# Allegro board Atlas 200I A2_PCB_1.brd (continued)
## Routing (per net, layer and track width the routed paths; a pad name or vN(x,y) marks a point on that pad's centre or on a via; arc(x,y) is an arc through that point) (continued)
HDMI0_TXC_P: length 58.3
  TOP w0.155: v1(65.62,16.61) 65.38,16.37 65.38,16.15 R332.1 ; J16.224 41.75,49.7 41.69,49.76 41.69,50.58 v1(41.96,50.85)
  ART04 w0.14: v1(41.96,50.85) 41.71,50.6 41.71,45.32 40.65,44.26 39.71,44.26 39.54,44.09 39.54,43.79 39.71,43.62 40.65,43.62 41.03,43.24 41.61,41.85 41.37,41.27 40.89,41.07 40.81,40.87 40.93,40.59 41.13,40.5 41.61,40.7 42.11,40.49 42.2,40.27 42.55,39.93 42.75,39.93 43.29,40.47 43.86,40.47 44.29,40.03 44.29,39.47 43.75,38.93 43.75,38.72 45.44,37.04 46.08,36.77 48.25,36.77 49.27,35.75 49.27,35.22 49.64,34.85 51.89,33.92 53.04,33.92 58.52,31.65 59.64,30.9 60.5,30.54 63.24,28.71 64.7,26.53 65.69,24.12 65.96,22.79 65.96,19.71 65.38,18.32 65.38,16.85 v1(65.62,16.61)
HDMI1_CEC: length 73.3
  TOP w0.203: J16.235 39,54.19 39.45,53.75 v1(39.45,53.19) ; v1(75.95,16.1) 75.95,15.11 76.15,14.91 R299.1 R298.2
  ART03 w0.203: v1(39.45,53.19) 39.93,52.7 41.49,52.7 42.02,53.24 46.85,53.24 47.9,52.19 47.9,45.67 49.35,44.22 51.41,44.22 52.93,42.7 53.58,42.7 54.69,41.59 54.69,40.89 55.02,40.56 55.02,34.77 55.32,34.46 55.32,33.57 56.99,31.9 61.12,31.9 62.65,30.38 v1(62.65,29.79)
  BOTTOM w0.203: v1(62.65,29.79) 62.65,29.82 63.07,30.24 63.07,30.24 63.07,30.41 63.65,30.99 67.94,30.99 70.33,28.59 70.33,27.54 77.22,20.66 77.22,17.38 v1(75.95,16.1)
HDMI1_HOTPLUG: length 81.7
  TOP w0.203: v1(78.79,17.65) 78.92,17.78 83.13,17.78 83.74,17.17 R304.2 C145.1 83.77,15.57 R305.2 R303.1 ; v1(39.47,54.46) 39.5,54.49 J16.233
  ART03 w0.203: v1(65.1,29.82) 65.1,30.28 63.96,31.42 62.76,31.42 60.82,33.35 58.08,33.35 57.1,34.33 57.1,34.35 56.83,34.62 56.81,34.62 56.19,35.25 56.19,37.51 56.34,37.66 56.34,38.04 56.11,38.26 56.11,43.55 54.16,45.49 49.23,45.49 48.82,45.9 48.82,52.42 47.16,54.08 39.85,54.08 v1(39.47,54.46)
  BOTTOM w0.203: v1(65.1,29.82) 65.1,30.38 65.3,30.58 67.77,30.58 69.93,28.42 69.93,27.37 75.21,22.09 75.21,20.52 76.17,19.56 76.17,17.32 75.49,16.64 75.49,15.91 75.76,15.65 76.78,15.65 v1(78.79,17.65)
HDMI1_SCL: length 51.6
  TOP w0.203: J16.27 91,53.57 v1(89.35,51.92) ; R300.1 v1(75.95,13.89) R297.2
  ART03 w0.203: v1(75.95,13.89) 75.46,14.38 75.46,26.12 v1(85.06,35.72)
  ART04 w0.203: v1(85.06,35.72) 85.06,36.94 90.22,42.1 90.22,45.82 90.73,46.33 90.73,47.51 89.31,48.93 89.31,51.88 v1(89.35,51.92)
HDMI1_SDA: length 53
  TOP w0.203: R301.1 v1(75.95,12.88) R302.2 ; J16.29 90.5,54.34 v1(89.35,53.19)
  ART03 w0.203: v1(75.95,12.88) 76.81,13.74 76.81,17.25 76.19,17.87 76.19,25.21 85.06,34.09 v1(85.06,34.45)
  ART04 w0.203: v1(85.06,34.45) 85.7,35.09 85.7,36.03 89.48,39.82 89.48,40.72 90.67,41.91 90.67,45.49 91.19,46 91.19,47.7 89.77,49.12 89.77,51.29 89.83,51.36 89.83,52.7 v1(89.35,53.19)
HDMI1_TX0_C_N: length 6.1
  TOP w0.155: R364.2 87.35,15.27 87.35,15 87.73,14.62 87.98,14.62 88.14,14.47 88.14,14.09 D23.7 D23.4 88.08,12.85 88.22,12.7 88.22,12.4 87.98,12.16 J7.9
HDMI1_TX0_C_P: length 6
  TOP w0.155: J7.7 88.98,12.44 88.58,12.84 D23.5 D23.6 88.52,14.09 88.52,14.63 88.14,15 87.89,15 87.73,15.16 87.73,15.44 R397.2
HDMI1_TX0_N: length 44.2
  TOP w0.155: J16.17 93.5,54.97 93.56,54.91 93.56,52.65 v1(93.29,52.37) ; R364.1 87.27,16.7 87.27,17.88 v1(87,18.15)
  ART04 w0.14: v1(93.29,52.37) 93.81,51.85 93.81,47.33 93.4,46.35 93.4,36.52 91.06,34.17 90.31,33.86 89.64,33.2 88.7,30.93 88.7,29.88 89.12,29.47 89.12,29.04 88.7,28.63 88.7,27.85 89.12,27.44 89.12,27.01 88.7,26.6 88.7,25.82 89.12,25.4 89.12,24.98 88.7,24.57 88.7,20.87 87.27,19.44 87.27,18.42 v1(87,18.15)
HDMI1_TX0_P: length 44.3
  TOP w0.155: R397.1 87.65,16.7 87.65,17.88 v1(87.91,18.15) ; J16.15 94,54.95 93.94,54.89 93.94,52.64 v1(94.21,52.37)
  ART04 w0.14: v1(87.91,18.15) 87.66,18.4 87.66,19.26 89.09,20.69 89.09,21.38 89.28,21.57 89.28,22.01 89.09,22.2 89.09,22.62 89.28,22.81 89.28,23.25 89.09,23.44 89.09,24.39 89.5,24.8 89.5,25.58 89.09,25.99 89.09,26.42 89.5,26.83 89.5,27.62 89.09,28.03 89.09,28.45 89.5,28.86 89.5,29.65 89.09,30.06 89.09,30.81 89.98,32.97 90.53,33.52 91.28,33.84 93.78,36.34 93.78,46.24 94.19,47.22 94.19,52.35 v1(94.21,52.37)
HDMI1_TX1_C_N: length 5.5
  TOP w0.155: J7.6 89.48,12.4 89.63,12.55 D21.1 D21.10 89.63,14.36 89.68,14.41 89.68,15.34 R360.2
HDMI1_TX1_C_P: length 5.6
  TOP w0.155: R361.2 90.06,15.38 90.06,14.4 90.13,14.34 D21.9 D21.2 90.07,13.14 90.07,12.5 90.48,12.09 J7.4
HDMI1_TX1_N: length 44.9
  TOP w0.155: v1(94.79,53.82) 95.06,54.09 95.06,54.91 95,54.97 J16.11 ; R360.1 89.66,16.7 89.66,17.37 89.51,17.53 v1(89.4,17.53)
  ART04 w0.14: v1(94.79,53.82) 95.07,53.53 95.07,49.06 95.32,48.47 95.32,44.67 94.47,43.82 94.47,33.78 93,32.31 93,30.94 92.83,30.77 92.75,30.77 92.37,30.4 92.37,29.74 92.75,29.37 92.83,29.37 93,29.2 93,28.91 92.83,28.74 92.75,28.74 92.37,28.36 92.37,27.71 92.75,27.34 92.83,27.34 93,27.17 93,26.87 92.83,26.7 92.75,26.7 92.37,26.33 92.37,25.68 92.75,25.31 92.83,25.31 93,25.14 93,23.28 90.92,21.2 90.63,21.2 90.34,20.9 90.34,20.62 89.65,19.93 89.65,17.77 v1(89.4,17.53)
HDMI1_TX1_P: length 44.8
  TOP w0.155: v1(95.71,53.82) 95.44,54.09 95.44,54.89 95.5,54.95 J16.9 ; v1(90.31,17.53) 90.2,17.53 90.05,17.37 90.05,16.7 R361.1
  ART04 w0.14: v1(95.71,53.82) 95.45,53.56 95.45,49.14 95.7,48.54 95.7,44.51 94.85,43.67 94.85,33.6 93.38,32.13 93.38,30.76 93.01,30.39 92.93,30.39 92.76,30.22 92.76,29.92 92.93,29.75 93.01,29.75 93.38,29.38 93.38,28.73 93.01,28.36 92.93,28.36 92.76,28.18 92.76,27.89 92.93,27.72 93.01,27.72 93.38,27.35 93.38,26.69 93.01,26.32 92.93,26.32 92.76,26.15 92.76,25.86 92.93,25.69 93.01,25.69 93.38,25.32 93.38,23.1 90.03,19.75 90.03,17.81 v1(90.31,17.53)
HDMI1_TX2_C_N: length 6.2
  TOP w0.155: R349.2 92.1,15.32 92.1,15.14 91.97,15.01 91.63,15.01 91.13,14.51 D21.7 D21.4 91.08,13.15 91.08,12.75 91.19,12.65 91.19,12.24 90.98,12.04 J7.3
HDMI1_TX2_C_P: length 6.1
  TOP w0.155: J7.1 91.98,11.79 92,11.81 92,12.32 91.63,12.69 D21.5 D21.6 91.63,14.47 91.79,14.63 92.18,14.63 92.48,14.94 92.48,15.4 R359.2
HDMI1_TX2_N: length 44.7
  TOP w0.155: J16.5 96.5,54.97 96.56,54.91 96.56,52.65 v1(96.29,52.37) ; v1(91.8,18.15) 92.06,17.88 92.06,16.7 R349.1
  ART04 w0.14: v1(96.29,52.37) 96.55,52.11 96.55,51.69 97.74,50.5 97.74,46.28 99.71,44.32 100.69,41.94 100.69,33.69 99.84,31.63 97.77,28.54 97.77,28.54 95.69,25.42 94.75,23.16 92.05,20.46 92.05,18.4 v1(91.8,18.15)
HDMI1_TX2_P: length 44.7
  TOP w0.155: R359.1 92.44,16.7 92.44,17.88 v1(92.71,18.15) ; v1(97.21,52.37) 96.94,52.64 96.94,54.89 97,54.95 J16.3
  ART04 w0.14: v1(92.71,18.15) 92.71,18.17 92.44,18.44 92.44,20.3 95.08,22.94 96.03,25.24 100.18,31.45 101.07,33.62 101.07,42.02 100.03,44.54 98.13,46.44 98.13,50.66 96.93,51.85 96.93,52.09 v1(97.21,52.37)
HDMI1_TX_5V: length 17.3
  TOP w0.203: 80.26,13.26 C144.1 81.61,12.75 82.32,13.46 R303.2 82.96,12.88 v1(82.88,12.8) 83.48,12.2 J7.18 ; 80.26,13.26 80.14,13.39 78.65,13.39 78.36,13.09 78.36,12.45 77.57,11.66 76.93,11.66 76.62,11.35 D25.3 75.34,11.35 74.45,12.24 R302.1 R297.1 ; 80.26,13.26 80.54,13.54 U29.5
HDMI1_TX_CEC: length 14.2
  TOP w0.203: v1(85.46,12.82) 85.46,12.23 85.98,11.71 J7.13 ; R299.2 78.16,15.6 78.16,15.98 78.71,16.54 78.71,16.55 v1(78.77,16.61) 78.98,16.82 U29.3
  ART03 w0.203: v1(85.46,12.82) 85.46,12.93 84.85,13.54 84.12,13.54 83.46,14.2 81.19,14.2 v1(78.77,16.61)
HDMI1_TX_DDC_SCL_C: length 13.1
  TOP w0.203: U29.6 81.49,15.16 81.29,15.37 78.99,15.37 78.16,14.53 78.16,14.35 77.7,13.89 R300.2 ; J7.15 v1(84.98,12)
  TOP w0.254: U29.6 v1(81.49,13.38)
  ART03 w0.203: v1(84.98,12) 84.98,12.76 84.66,13.08 83.93,13.08 83.27,13.74 81.86,13.74 v1(81.49,13.38)
HDMI1_TX_DDC_SDA_C: length 12
  TOP w0.203: U29.4 v1(78.8,14.37) 78.8,14.26 77.9,13.36 77.9,13.08 77.7,12.88 R301.2 ; J7.16 v1(84.48,12.58)
  ART03 w0.203: v1(84.48,12.58) 84.45,12.61 83.75,12.61 83.08,13.28 82.35,13.28 81.96,12.89 80.27,12.89 v1(78.8,14.37)
HDMI1_TX_HPD_C: length 12.9
  TOP w0.203: R304.1 v1(82.31,16.61) 82.1,16.82 U29.1 ; J7.19 v1(82.98,12)
  ART03 w0.203: v1(82.31,16.61) 82.31,15.92 84.29,13.95 85.02,13.95 85.92,13.04 85.92,12.25 85.18,11.51 83.46,11.51 v1(82.98,12)
HDMI1_TXC_C_N: length 6.9
  TOP w0.155: R339.2 84.86,15.36 84.86,15.06 85.37,14.55 86.41,14.55 86.58,14.38 D23.10 D23.1 86.58,12.82 86.28,12.51 86.28,12.29 86.48,12.09 J7.12
HDMI1_TXC_C_P: length 7
  TOP w0.155: J7.10 87.48,12.06 87.25,12.29 87.25,12.29 87.02,12.52 87.02,13.14 D23.2 D23.9 87.08,14.42 86.57,14.93 85.53,14.93 85.24,15.22 85.24,15.36 R343.2
HDMI1_TXC_N: length 43.9
  TOP w0.155: v1(91.79,53.82) 92.06,54.09 92.06,54.91 92,54.97 J16.23 ; v1(84.6,17.53) 84.71,17.53 84.87,17.37 84.87,16.7 R339.1
  ART04 w0.14: v1(84.6,17.53) 84.88,17.81 84.88,19.22 86.2,20.54 86.2,31.72 89.97,35.49 89.97,39.13 90.43,40.23 91.3,41.09 91.3,44.99 91.92,45.62 91.92,48.43 91.32,49.03 91.32,52.47 92.06,53.21 92.06,53.54 v1(91.79,53.82)
HDMI1_TXC_P: length 43.9
  TOP w0.155: v1(92.71,53.82) 92.44,54.09 92.44,54.89 92.5,54.95 J16.21 ; R343.1 85.25,16.7 85.25,17.37 85.4,17.53 v1(85.51,17.53)
  ART04 w0.14: v1(85.51,17.53) 85.27,17.77 85.27,19.04 86.58,20.36 86.58,31.54 90.36,35.31 90.36,39.01 90.77,40 91.68,40.91 91.68,44.81 92.3,45.44 92.3,48.59 91.7,49.19 91.7,52.29 92.45,53.03 92.45,53.55 v1(92.71,53.82)
HDMI_TX_3V3: length 30.3
  TOP w0.203: v1(74.78,17.68) 75.77,16.69 77.09,16.69 77.47,16.31 ; R298.1 77.47,16.31 ; 77.47,16.31 C146.1
  TOP w0.254: R280.1 v1(64.87,23.32) 64.87,26.3 63.8,27.36 63.8,28.8 64.37,29.36 C143.1 64.37,30.34 65.45,31.42 66.88,31.42 67.69,32.23 D18.3
  BOTTOM w0.203: v1(74.78,17.68) 70.51,17.68 v1(64.87,23.32)
HOT_RST_FAULT: length 13.2
  TOP w0.203: J16.295 104.5,54.8 v1(104.85,54.46) ; R479.2 105.94,44.38 106.42,44.85 v1(106.5,44.85)
  ART04 w0.203: v1(104.85,54.46) 104.85,53.91 106.07,52.69 106.07,49.06 106.5,48.63 v1(106.5,44.85)
HUB_1V2_SWR: length 17
  TOP w0.203: v1(93.6,83.73) 93.6,83.78 93.75,83.93 U36.52
  ART04 w0.203: v1(93.6,83.73) 93.97,83.36 101.52,83.36 102.63,84.47 107.76,84.47 v1(108.66,83.57)
I2C6_SCL: length 216.8
  TOP w0.203: J16.6 96.25,50.25 96.65,50.64 v1(96.65,50.8) ; R442.1 123.14,90.04 v1(123.07,90.04) ; v1(5.12,86.31) 4.85,86.31 4.44,86.72 R61.2
  ART03 w0.203: v1(13.21,82.68) 13.69,83.16 14.55,83.16 14.83,82.88 14.83,82.48 14.73,82.38 14.73,80.21 15.57,79.38 23.75,79.38 27.44,83.07 27.44,86.31 28.99,87.85 35.27,87.85 37.02,89.6 37.02,93.85 37.74,94.56 39.9,94.56 40.82,93.65 50.06,93.65 53.65,90.07 59.44,90.07 64.67,95.3 68.57,95.3 69.89,96.62 70.87,96.62 71.68,97.43 76.86,97.43 78.87,95.42 78.87,91.8 79.88,90.78 80.21,90.78 80.92,90.07 86.03,90.07 86.66,90.7 v1(87.33,90.7) ; v1(96.65,50.8) 97.98,52.14 97.98,58.08 97.66,58.4 97.66,61.97 98.93,63.25 98.93,66.84 101.27,69.17 101.27,69.92 100.94,70.25 100.94,73.74 v1(101.42,74.22)
  ART04 w0.203: v1(13.21,82.68) 12.19,83.69 7.27,83.69 5.12,85.85 v1(5.12,86.31) ; v1(87.33,90.7) 89.06,92.44 89.06,93.04 89.54,93.52 91.78,93.52 92.09,93.83 97.82,93.83 99.01,95.02 104.01,95.02 106.45,92.58 120.53,92.58 v1(123.07,90.04) 124.59,88.53 124.59,77.11 122.66,75.18 110.71,75.18 110.1,75.79 108.76,75.79 108.35,75.39 103.1,75.39 101.93,74.22 v1(101.42,74.22)
I2C6_SDA: length 211.9
  TOP w0.203: v1(123.07,84.08) 123.14,84.08 R449.2 ; J16.4 96.75,50.11 97.29,50.64 97.29,50.96 v1(98.86,52.53) ; v1(6.08,86.36) 6.15,86.43 R60.2
  ART03 w0.203: v1(101.42,75.11) 101.96,74.57 101.96,69.21 99.42,66.67 99.42,63 98.12,61.7 98.12,58.59 98.5,58.21 98.5,52.9 v1(98.86,52.53) ; v1(86.87,89.18) 86.54,89.51 79.85,89.51 77.95,91.4 77.95,95.6 77.39,96.16 70.08,96.16 68.76,94.84 64.86,94.84 59.63,89.61 53.46,89.61 49.87,93.19 40.46,93.19 39.55,94.11 37.93,94.11 37.48,93.66 37.48,88.15 35.89,86.56 30.38,86.56 27.9,84.08 27.9,82.88 23.94,78.92 15.38,78.92 14.03,80.27 14.03,82.35 v1(14.35,82.68)
  ART04 w0.203: v1(101.42,75.11) 102.39,76.07 103.4,76.07 104.27,76.94 106.96,76.94 107.57,77.55 109.68,77.55 110.2,77.02 120.51,77.02 122.87,79.39 123.21,79.39 123.56,79.74 123.56,83.6 v1(123.07,84.08) 123.07,84.39 122.35,85.12 122.35,87.18 120.63,88.9 118.98,88.9 116.21,91.67 109.32,91.67 109.27,91.62 106.43,91.62 103.53,94.51 99.59,94.51 97.3,92.22 96.28,91.8 95.2,91.8 93.29,92.58 91.75,92.58 91.27,93.07 90.87,93.07 90.59,92.78 90.59,91.6 89.49,90.5 87.83,90.5 86.87,89.53 v1(86.87,89.18) ; v1(6.08,86.36) 6.08,85.69 7.44,84.33 12.7,84.33 v1(14.35,82.68)
I2C7_SCL: length 81.8
  TOP w0.203: R601.2 v1(97.92,114.05) R595.1 ; v1(99.94,52.55) 99.67,52.55 97.86,50.74 97.86,50.6 97.25,49.98 J16.2
  ART03 w0.203: v1(97.92,114.05) 98.37,114.05 98.81,113.61 98.81,113.47 99.73,112.54 106.66,112.54 109.13,110.08 109.13,106.02 110.08,105.06 110.08,102.08 109.42,101.42 109.42,92.89 109.55,92.76 109.55,91.46 108.18,90.09 108.18,88.9 107.54,88.27 107.54,84.49 105.99,82.94 105.99,81.96 105.16,81.12 105.16,70.14 100.98,65.96 100.98,57.44 100.74,57.19 100.74,53.34 v1(99.94,52.55)
I2C7_SCL_HUB0: length 48
  TOP w0.203: v1(85.29,103.63) 85.49,103.43 U38.36 ; v1(104.14,82.22) 103.73,82.63 R597.1
  ART03 w0.203: v1(104.14,82.22) 103.68,82.68 103.68,84.5 104.34,85.16 104.34,91.05 105.36,92.07 105.36,97.22 100.52,102.06 98.73,102.06 98.12,102.67 95.29,102.67 94.65,102.02 93.36,102.02 91.57,103.82 91.57,107.51 91.59,107.53 91.59,107.91 91.32,108.18 90.95,108.18 90.68,107.91 90.68,107.11 88.57,105 86.57,105 86.23,104.67 86.23,104.41 85.46,103.63 v1(85.29,103.63)
I2C7_SCL_HUB1: length 2.2
  TOP w0.203: R592.1 101.42,82.22 U36.34
I2C7_SCL_R: length 82.8
  TOP w0.188: R597.2 102.64,82.78 103.1,83.24 104.1,83.24 v1(104.2,83.13)
  TOP w0.203: U22.7 89.11,113.24 88.7,112.83 v1(88.7,112.65) 88.7,112.62 88.49,112.42 R599.1 ; v1(123.07,70.95) 123.68,70.95 R445.2
  ART03 w0.203: v1(104.2,83.13) 104.25,83.13 106.17,85.06 106.17,91.08 106.63,91.54 106.63,100.48 101.2,105.91 100.54,105.91 100.34,105.71 100.34,104.7 100.14,104.5 99.73,104.5 99.53,104.7 99.53,105.71 99.32,105.91 98.92,105.91 98.71,105.71 98.71,104.7 98.51,104.5 98.1,104.5 97.9,104.7 97.9,105.71 97.7,105.91 95.38,105.91 v1(93.09,108.2) 93.09,109.5 89.94,112.65 v1(88.7,112.65)
  ART04 w0.203: v1(123.07,70.95) 121.99,72.03 120.14,72.03 118.36,73.81 108.89,73.81 108.54,74.17 v1(103.12,74.17)
  BOTTOM w0.203: v1(104.2,83.13) 104.67,82.67 104.67,81.89 104.22,81.43 104.22,77.04 103.12,75.95 v1(103.12,74.17)
I2C7_SDA: length 81
  TOP w0.203: v1(99.16,51.31) 97.75,49.9 J16.320 ; R596.1 97.79,115.06 v1(97.92,114.94) 98.04,115.06 R602.2
  ART03 w0.203: v1(97.92,114.94) 97.43,114.45 97.43,113.85 99.2,112.08 105.82,112.08 108.51,109.4 108.51,92.86 107.95,92.3 107.95,90.69 107.09,89.83 107.09,84.68 105.54,83.13 105.54,82.15 103.81,80.42 103.81,72.59 103.12,71.9 103.12,69.09 100.42,66.38 100.42,59.7 100.02,59.3 100.02,57.44 100.05,57.4 100.05,53.34 99.46,52.75 99.46,51.61 v1(99.16,51.31)
I2C7_SDA_HUB0: length 47.2
  TOP w0.203: U38.37 85.09,103.12 84.58,103.63 v1(84.58,104.22) ; R593.1 104.09,83.96 v1(104.14,84.01)
  ART03 w0.203: v1(104.14,84.01) 104.36,84.01 105.71,85.37 105.71,91.27 106.17,91.73 106.17,100.29 102.59,103.87 95.28,103.87 92.05,107.11 92.05,107.74 92.02,107.76 92.02,108.05 91.49,108.58 90.78,108.58 89.02,106.83 87.2,106.83 v1(84.58,104.22)
I2C7_SDA_HUB1: length 3
  TOP w0.203: R590.1 101.54,83.96 101.09,83.52 101.09,82.83 100.88,82.62 U36.35
I2C7_SDA_R: length 85.5
  TOP w0.188: R590.2 102.64,83.82 102.43,83.61 v1(102.43,83.29)
  TOP w0.203: U22.6 89.05,113.89 v1(88.7,113.54) 88.43,113.27 R600.1 ; R444.2 123.68,69.12 v1(123.07,69.12)
  ART03 w0.203: v1(88.7,113.54) 89.7,113.54 93.83,109.41 93.83,108.43 v1(94.06,108.2) 95.72,106.54 101.22,106.54 107.09,100.67 107.09,91.35 106.63,90.89 106.63,84.87 105.08,83.32 105.08,82.48 104.34,81.74 103.52,81.74 102.43,82.83 v1(102.43,83.29)
  ART04 w0.203: v1(101.42,73.03) 108.39,73.03 108.51,72.9 115.24,72.9 119.02,69.12 v1(123.07,69.12)
  BOTTOM w0.203: v1(102.43,83.29) 102.18,83.05 102.18,80.92 102.74,80.37 102.74,78.44 100.89,76.58 100.89,73.56 v1(101.42,73.03)
I2C8_SCL: length 221.6
  TOP w0.203: v1(86.65,116.98) 87.22,116.98 R490.1 R496.2 ; R58.2 v1(5.29,88.44) ; J16.318 98.25,49.75 99.46,50.96 99.62,50.96 v1(99.94,51.28)
  ART03 w0.203: v1(37.72,109.73) 37.23,109.24 37.23,108.57 40.26,105.54 76.43,105.54 82.58,111.68 82.58,114.58 84.98,116.98 v1(86.65,116.98) 86.16,116.5 86.16,115.76 86.92,115.01 93.73,115.01 94.16,114.58 96.88,114.58 97.72,115.42 98.12,115.42 99.26,114.27 99.26,113.66 99.92,113 106.85,113 109.58,110.27 109.58,106.2 110.54,105.25 110.54,92.16 110.16,91.78 110.16,91.3 108.64,89.78 108.64,87.6 108,86.97 108,84.3 106.65,82.95 106.65,81.64 106.07,81.05 106.07,76.76 106.43,76.4 106.43,70.66 101.58,65.82 101.58,54.86 101.7,54.73 101.7,53.04 v1(99.94,51.28)
  ART04 w0.203: v1(37.72,109.73) 37.72,114.73 33.73,118.72 20.71,118.72 16.19,114.2 10.49,114.2 5.84,109.55 5.84,104.8 3.59,102.55 3.59,92.47 4.62,91.44 4.62,89.11 v1(5.29,88.44)
I2C8_SCL_R: length 32.3
  TOP w0.203: R493.2 v1(97.95,117.36) 97.95,117.64 R494.1
  TOP w0.254: R499.2 v1(114.68,100.56) ; R482.2 v1(112.12,102.36)
  ART03 w0.203: v1(112.12,102.36) 112.78,103.01 112.78,105.02 111.03,106.77 111.03,111.44 107.91,114.55 101.52,114.55 98.72,117.36 v1(97.95,117.36)
  BOTTOM w0.203: v1(112.12,102.36) 113.06,102.36 114.68,100.74 v1(114.68,100.56)
I2C8_SDA: length 220.5
  TOP w0.203: J16.316 98.75,49.63 99.26,50.14 v1(99.94,50.14) ; R59.2 v1(7,88.44) ; R497.2 R491.1 v1(86.65,115.96)
  ART03 w0.203: v1(37.72,108.84) 40.39,106.17 76.42,106.17 82.12,111.87 82.12,114.91 84.67,117.46 86.85,117.46 87.13,117.18 87.13,116.45 v1(86.65,115.96) 86.97,115.64 91.69,115.64 92.06,116.01 93.74,116.01 94.11,115.65 97.3,115.65 97.53,115.87 98.41,115.87 99.72,114.56 99.72,113.85 100.11,113.45 107.04,113.45 110.04,110.46 110.04,106.39 111,105.44 111,91.97 110.62,91.59 110.62,91.11 109.09,89.59 109.09,89.19 109.45,88.83 109.45,83.67 108.25,82.47 108.21,82.47 107.49,81.76 107.49,76.6 107.7,76.4 107.7,71.29 102.04,65.63 102.04,62.78 103.09,61.72 103.09,53.29 v1(99.94,50.14)
  ART04 w0.203: v1(7,88.44) 5.08,90.37 5.08,91.63 4.05,92.66 4.05,101.13 8.46,105.54 8.46,111.52 10.68,113.74 16.41,113.74 20.42,117.75 33.07,117.75 35.89,114.93 35.89,110.67 v1(37.72,108.84)
I2C8_SDA_R: length 34.1
  TOP w0.203: R495.1 97.95,116.63 v1(97.95,116.47) 97.82,116.35 R492.2
  TOP w0.254: R481.2 v1(112.12,103.38) ; R498.2 v1(118.59,100.56)
  ART03 w0.203: v1(112.12,103.38) 112.12,104.96 110.5,106.58 110.5,110.93 107.52,113.91 101.02,113.91 98.46,116.47 v1(97.95,116.47)
  BOTTOM w0.203: v1(118.59,100.56) 116.46,100.56 114.66,102.36 114.66,102.56 114.38,102.84 112.66,102.84 v1(112.12,103.38)
I2S0_BCLK: length 120.8
  TOP w0.203: R53.1 v1(118.8,79.9) ; J16.261 32.5,52.69 v1(32.38,52.58) ; v1(51.03,67.18) 51.03,67.77 52.09,68.83 59.81,68.83 70.3,79.32 71.3,79.32 71.63,79.65 71.63,80.94 69.48,83.09 v1(67.41,83.09)
  ART04 w0.203: v1(118.8,79.9) 115.24,83.46 110.82,83.46 109,85.28 106.46,85.28 105.59,86.16 105.07,86.16 104.89,85.98 102.42,85.98 101.53,85.09 92.62,85.09 92.14,84.6 89.63,84.6 88.52,85.06 88.16,85.43 88.16,85.93 87.82,86.27 87.06,86.27 86.66,85.87 84.95,85.87 84.5,85.42 75.77,85.42 73.93,83.58 73.69,83.58 72.87,82.77 67.73,82.77 v1(67.41,83.09)
  BOTTOM w0.203: v1(51.03,67.18) 43.47,67.18 40.36,64.07 40.36,61.95 32.38,53.98 v1(32.38,52.58)
I2S0_BCLK_R: length 23.6
  TOP w0.203: v1(119.08,87.85) 118.76,88.18 U35.13 ; v1(123.07,71.81) 123.68,71.81 R454.1
  ART03 w0.203: v1(123.07,71.81) 123.43,72.16 123.43,73.05 122.51,73.97 122.51,79 122.88,79.36 123.15,79.36 123.56,79.77 123.56,86.47 123.55,86.47 123.55,87.34 123.26,87.62 122.55,87.62 122.32,87.39 119.54,87.39 v1(119.08,87.85)
I2S0_LRCK: length 121.6
  TOP w0.203: J16.259 33,57.5 32.77,57.73 v1(32.38,57.73) ; v1(66.01,83.09) 65.57,82.65 62.88,82.65 54.79,79.3 51.61,76.12 51.61,75.83 52.02,75.43 52.02,75.14 51.73,74.85 51.44,74.85 51.03,75.26 50.75,75.26 50.46,74.97 50.46,74.68 50.87,74.28 50.87,73.99 50.58,73.7 50.29,73.7 49.88,74.11 49.6,74.11 49.11,73.62 49.11,72.86 48.68,72.43 48.11,72.43 47.57,71.89 47.57,71.6 48.57,70.6 48.57,70.31 48.14,69.88 47.85,69.88 46.85,70.88 46.57,70.88 46.14,70.45 46.14,70.16 47.13,69.16 47.13,68.88 46.7,68.44 46.41,68.44 45.42,69.44 45.13,69.44 44.7,69.01 44.7,68.72 45.7,67.73 45.7,67.44 45.27,67.01 44.98,67.01 43.98,68.01 43.69,68.01 43.26,67.57 43.26,67.13 43.06,66.93 v1(40.51,66.93) ; R557.1 v1(119.91,79.9)
  ART03 w0.203: v1(40.51,66.93) 40.41,66.93 39.26,65.78 36.96,60.22 35.82,59.08 34.78,58.65 33.88,57.76 33.83,57.76 33.8,57.73 v1(32.38,57.73)
  ART04 w0.203: v1(66.01,83.09) 66.54,83.62 72.58,83.62 73.68,84.71 74.07,84.71 75.39,86.03 80.77,86.03 81.56,86.82 83.03,86.82 83.06,86.79 86.72,86.79 86.8,86.88 88.14,86.88 88.79,86.23 88.79,85.6 88.97,85.43 89.47,85.22 91.89,85.22 92.37,85.7 101.27,85.7 103.38,87.81 104.09,87.81 105.13,86.77 106.25,86.77 107.12,85.89 109.26,85.89 110.44,84.71 115.75,84.71 119.91,80.55 v1(119.91,79.9)
I2S0_LRCK_R: length 15.8
  TOP w0.203: R453.2 122.94,102.62 v1(122.87,102.62) ; v1(119.08,90.63) 119.41,90.3 U35.12
  ART03 w0.203: v1(122.87,102.62) 122.63,102.62 119.08,99.07 v1(119.08,90.63)
I2S0_MCLK: length 116.3
  TOP w0.203: v1(32.38,51.82) 32.38,51.93 31.93,52.39 31.93,52.77 32,52.84 J16.263 ; v1(67.41,80.43) 66.95,79.97 64.41,79.97 63.59,80.78 61.12,80.78 58.86,79.84 50.29,71.28 50.29,70.49 43.5,63.7 v1(41.27,63.7) ; R671.1 v1(113.09,68.23)
  ART04 w0.203: v1(67.41,80.43) 66.95,80.88 65.83,80.88 64.54,79.6 64.54,76.48 65.61,75.41 69.08,75.41 69.41,75.74 71.3,75.74 71.63,75.41 77.6,75.41 79.91,73.1 80.83,73.1 81.1,72.83 81.1,72.49 82.94,70.66 84.64,70.66 87.6,67.7 97.55,67.7 100.03,70.18 101.19,70.18 101.78,69.6 107.99,69.6 109.84,67.75 112.61,67.75 v1(113.09,68.23)
  BOTTOM w0.203: v1(41.27,63.7) 41.27,61.52 34.45,54.7 32.86,52.29 v1(32.38,51.82)
I2S0_MCLK_R: length 13.3
  TOP w0.203: R288.2 v1(122.57,72.66) ; U33.13 113.05,76.51 v1(113.37,76.18)
  ART03 w0.203: v1(113.37,76.18) 114.14,75.41 119.82,75.41 v1(122.57,72.66)
I2S0_MISO: length 120.2
  TOP w0.203: J16.255 34,57.17 34.24,58.37 34.63,58.96 34.98,59.79 v1(35.48,60.54) ; v1(66.27,84.62) 65.55,85.33 64.94,85.33 64.34,84.73 63.99,84.73 63.79,84.53 63.79,84.07 63.59,83.87 62.47,83.87 61.77,83.58 61.5,83.69 61.19,84.44 60.93,84.55 60.36,84.31 60.25,84.05 60.56,83.3 60.45,83.03 59.89,82.8 59.63,82.91 59.32,83.66 59.05,83.77 58.49,83.53 58.38,83.27 58.69,82.52 58.58,82.26 58.01,82.02 57.75,82.13 57.44,82.88 57.17,82.99 56.61,82.76 56.5,82.49 56.81,81.74 56.7,81.48 56.14,81.25 55.87,81.36 55.56,82.1 55.3,82.21 54.73,81.98 54.62,81.71 54.93,80.97 54.82,80.7 54.04,80.38 51.3,77.64 51.01,77.64 50.9,77.75 50.61,77.75 50.33,77.46 50.33,77.17 50.44,77.06 50.44,76.78 50.15,76.49 49.86,76.49 49.75,76.6 49.46,76.6 49.18,76.31 49.18,76.02 49.29,75.91 49.29,75.63 49,75.34 48.71,75.34 48.6,75.45 48.31,75.45 48.03,75.16 48.03,74.87 48.14,74.76 48.14,74.48 47.57,73.91 47.35,73.39 42.41,68.45 v1(40.51,68.45) ; R572.1 v1(121.02,79.9)
  ART03 w0.203: v1(40.51,68.45) 40.21,68.45 37.72,65.96 v1(35.48,60.54)
  ART04 w0.203: v1(121.02,79.9) 121.02,80.83 116.53,85.32 110.69,85.32 109.51,86.5 107.37,86.5 106.5,87.38 105.59,87.38 104.19,88.77 101.57,88.77 99.94,87.14 94.02,87.14 92.29,88.86 89.2,88.86 88.93,88.59 88.93,88.19 88.26,87.53 86.31,87.53 86.18,87.4 85.78,87.4 85.19,87.99 80.95,87.99 79.68,86.72 74.57,86.72 73.07,85.22 66.87,85.22 v1(66.27,84.62)
I2S0_MISO_R: length 18.8
  TOP w0.203: v1(122.87,105.66) 122.94,105.66 R455.1 ; v1(120.38,90.63) 120.06,90.3 U35.11
  ART03 w0.203: v1(120.38,90.63) 120.38,99.8 122.75,102.16 123.06,102.16 123.33,102.43 123.33,104.87 123.23,104.97 123.23,105.31 v1(122.87,105.66)
I2S0_MOSI: length 115
  TOP w0.203: v1(40.51,67.69) 42.52,67.69 47.93,73.11 48.13,73.58 54.31,79.76 62.76,83.26 64.62,83.26 65.15,83.79 66.65,83.79 v1(67.44,84.58) ; R556.1 122.13,80.03 v1(122,79.9) ; J16.257 33.5,58.32 v1(33.58,58.39)
  ART03 w0.203: v1(40.51,67.69) 40.31,67.69 38.36,65.74 36.11,60.32 35.56,59.76 34.52,59.33 v1(33.58,58.39) ; v1(80.3,79.89) 74.08,79.89 73.99,79.98 73.94,79.98 71.15,82.77 70.87,82.77 70.84,82.74 70.55,82.74 70.26,83.03 70.26,83.32 70.29,83.35 70.29,83.63 69.34,84.58 v1(67.44,84.58)
  ART04 w0.203: v1(122,79.9) 122,79.57 121.14,78.71 121.14,78.7 120.26,77.82 117.65,77.82 117.15,78.33 116.17,78.33 115.97,78.12 115.97,77.98 115.77,77.77 115.36,77.77 115.16,77.98 115.16,78.12 114.95,78.33 114.55,78.33 114.34,78.12 114.34,77.98 114.14,77.77 113.74,77.77 113.53,77.98 113.53,78.12 113.33,78.33 111.69,78.33 111.19,78.82 109.3,78.82 109.09,79.03 109.09,79.81 108.89,80.01 108.48,80.01 108.28,79.81 108.28,79.03 108.08,78.82 107.67,78.82 107.47,79.03 107.47,79.81 107.26,80.01 106.86,80.01 106.65,79.81 106.65,79.03 106.45,78.82 106,78.82 105.18,78 98.5,78 96.88,79.63 93.44,79.63 92.75,80.31 91.44,80.31 88.98,77.85 86.52,77.85 86.21,78.17 84.87,78.17 84.58,77.88 83.92,77.88 82.04,79.75 80.43,79.75 v1(80.3,79.89)
I2S0_MOSI_R: length 22.9
  TOP w0.203: U35.10 120.71,88.18 v1(120.38,87.85) ; v1(122.87,106.68) 122.94,106.68 R456.1
  ART03 w0.203: v1(122.87,106.68) 123.63,105.92 123.63,105.14 123.73,105.04 123.73,100.41 123.18,99.85 122.9,99.85 121.95,98.9 121.95,89.41 v1(120.38,87.85)
I2S1_BCLK: length 62.7
  TOP w0.203: v1(36.76,67.66) 36.76,66.68 39.1,64.34 39.1,62 35.5,58.4 J16.249 ; R55.2 v1(20.95,88.44)
  ART03 w0.203: v1(20.95,88.44) 19.53,89.87 18.39,89.87 17.88,90.37 17.48,90.37 13.95,86.84 13.44,86.84 10.77,84.18 10.77,81.1 18.13,73.74 30.23,73.74 36.3,67.66 v1(36.76,67.66)
I2S1_LRCK: length 59.7
  TOP w0.203: J16.247 36,58.17 39.51,61.67 39.51,64.63 37.49,66.64 37.49,68.2 v1(36.76,68.93) ; R45.2 v1(19.94,88.44)
  ART03 w0.203: v1(19.94,88.44) 19.33,89.05 17.31,89.05 14.14,85.88 13.82,85.88 11.38,83.43 11.38,81.12 14.86,77.65 16.48,77.65 19.99,74.14 31.55,74.14 v1(36.76,68.93)
I2S1_MCLK: length 105.1
  TOP w0.203: v1(66.01,80.43) 64.74,81.7 62.17,81.7 57.56,79.79 49.66,71.88 49.66,70.43 45.39,66.17 v1(40.51,66.17) ; R612.1 v1(114.2,68.23) ; J16.251 35,57.71 34.95,57.76 v1(34.95,57.77)
  ART03 w0.203: v1(40.51,66.17) 38.21,60.62 37.57,59.97 36.16,58.57 35.45,58.27 v1(34.95,57.77)
  ART04 w0.203: v1(114.2,68.23) 113.73,68.71 109.46,68.71 108.16,70 101.94,70 101.36,70.59 99.77,70.59 97.29,68.1 87.77,68.1 84.81,71.06 83.74,71.06 82.25,72.56 82.25,72.83 81.98,73.1 81.41,73.1 81,73.51 80.19,73.51 77.04,76.65 68.28,76.65 67.61,75.97 65.62,75.97 64.95,76.65 64.95,79.36 v1(66.01,80.43)
I2S1_MCLK_R: length 15.2
  TOP w0.203: v1(113.37,78.96) 113.7,78.64 U33.12 ; v1(123.07,86.14) 123.14,86.14 R450.2
  ART03 w0.203: v1(123.07,86.14) 122.76,85.83 119.48,85.83 113.65,79.99 113.65,79.24 v1(113.37,78.96)
I2S1_MISO: length 58.5
  TOP w0.203: v1(38.54,67.66) 38.54,67.28 40.49,65.33 40.49,61.14 37,57.65 J16.243 ; R62.2 v1(18.92,88.44)
  ART03 w0.203: v1(18.92,88.44) 17.42,86.94 17.42,86.12 15.07,83.77 13.44,83.77 12.6,82.93 12.6,81.05 15.19,78.46 17.4,78.46 18.14,77.72 29.75,77.72 37.88,69.6 38.71,69.6 39.22,69.09 39.22,68.34 v1(38.54,67.66)
I2S1_MOSI: length 58.1
  TOP w0.203: R63.2 v1(17.91,88.44) ; J16.245 36.5,57.81 39.98,61.29 39.98,64.91 37.97,66.92 37.97,68.36 v1(38.54,68.93)
  ART03 w0.203: v1(38.54,68.93) 37.68,68.93 30.52,76.1 18.64,76.1 16.69,78.05 15.02,78.05 11.99,81.09 11.99,83.18 13.19,84.38 14.82,84.38 16.6,86.16 16.6,87.13 v1(17.91,88.44)
LED_G: length 2.4
  TOP w0.203: R419.1 94.59,43.13 94.39,42.93 Q15.3
LED_HEALTHY_G: length 2.4
  TOP w0.203: Q13.3 79.91,43.94 80.11,44.14 R411.1
LED_HEALTHY_R: length 2.3
  TOP w0.203: R410.1 73.38,43.31 Q12.3
LED_R: length 2.4
  TOP w0.203: R418.1 87.35,43.25 87.02,42.93 Q14.3
LSADC0: length 5.8
  TOP w0.203: J16.312 99.75,47.09 99.11,46.44 97.12,46.44 R8.1
LSADC1: length 5.4
  TOP w0.203: J16.310 100.25,47.01 99.28,46.04 97.73,46.04 R9.1
M2_TYPE: length 48.3
  TOP w0.203: J16.315 99.5,54.59 v1(99.57,54.53) ; R15.2 123.67,25.07 R17.2 R16.1 v1(123.67,27.61)
  ART04 w0.203: v1(99.57,54.53) 101.89,52.21 101.89,48.47 100.48,47.06 100.48,45.92 101.98,44.43 101.98,42.92 105.13,39.77 105.13,36.62 109.78,31.98 112,31.98 116.37,27.61 v1(123.67,27.61)
MDI_PHY0_0_N: length 21.1
  TOP w0.155: T19.12 3.05,37.06 3.05,38.07 1.93,39.19 D33.1 1.93,41.48 2.38,41.92 2.38,44.18 1.93,44.63 D33.8 1.93,46.36 v1(2.1,46.53) ; R137.2 v1(9.49,47.73)
  ART04 w0.14: v1(9.49,47.73) 9.19,48.02 9.19,48.63 8.5,49.33 3.99,49.33 2.38,47.72 2.38,46.8 v1(2.1,46.53)
MDI_PHY0_0_P: length 20.7
  TOP w0.155: T19.11 4,38.16 3.2,38.96 D33.2 3.2,41.48 2.76,41.92 2.76,44.18 3.2,44.63 D33.7 3.2,46.36 v1(3.03,46.53) ; R136.2 v1(8.55,47.73)
  ART04 w0.14: v1(3.03,46.53) 2.76,46.8 2.76,47.56 4.15,48.95 4.47,48.95 4.61,48.81 4.61,48.68 4.75,48.54 5.03,48.54 5.17,48.68 5.17,48.81 5.31,48.95 6.94,48.95 7.08,48.81 7.08,48.65 7.22,48.51 7.5,48.51 7.64,48.65 7.64,48.81 7.78,48.95 8.34,48.95 8.81,48.47 8.81,47.99 v1(8.55,47.73)
MDI_PHY0_1_N: length 18.2
  TOP w0.155: v1(4.64,46.53) 4.47,46.36 D33.6 4.47,44.63 4.92,44.18 4.92,41.92 4.47,41.48 D33.3 4.47,39.22 5.08,38.61 5.41,38.61 6,38.02 T19.9 ; v1(9.14,44.78) 9.19,44.84 R130.2
  ART04 w0.14: v1(4.64,46.53) 4.92,46.8 4.92,47.16 5.28,47.52 7.04,47.52 8.86,45.69 8.86,45.05 v1(9.14,44.78)
MDI_PHY0_1_P: length 18
  TOP w0.155: v1(5.57,46.53) 5.74,46.36 D33.5 5.74,44.63 5.3,44.18 5.3,41.92 5.74,41.48 D33.4 5.74,39.19 7,37.93 T19.8 ; R131.2 8.21,45.48 v1(8.21,44.78)
  ART04 w0.14: v1(8.21,44.78) 8.48,45.05 8.48,45.54 8.28,45.74 8.08,45.74 7.95,45.61 7.73,45.61 7.54,45.8 7.54,45.99 7.69,46.14 7.69,46.33 7.6,46.42 7.4,46.42 7.26,46.28 7.06,46.28 6.86,46.48 6.86,46.68 7,46.82 7,47.02 6.88,47.14 6.51,47.14 6.33,46.96 5.95,46.96 5.77,47.14 5.44,47.14 5.3,47 5.3,46.8 v1(5.57,46.53)
MDI_PHY0_2_N: length 24.7
  TOP w0.155: v1(13.3,38.56) 13.13,38.73 D34.1 13.13,40.97 13.58,41.41 13.58,43.67 13.13,44.12 D34.8 13.13,46.31 v1(13.3,46.48) ; T19.6 v1(9,35.54) ; R132.2 11.71,44.76 v1(11.65,44.7)
  ART04 w0.14: v1(9,35.54) 9.31,35.85 9.31,36.21 10.04,36.93 10.73,36.93 10.87,37.07 10.87,37.33 11.01,37.47 11.29,37.47 11.43,37.33 11.43,37.07 11.57,36.93 11.85,36.93 11.99,37.07 11.99,37.33 12.13,37.47 12.4,37.47 12.54,37.33 12.54,37.07 12.68,36.93 13.05,36.93 13.58,37.46 13.58,38.28 v1(13.3,38.56) ; v1(13.3,46.48) 13.3,46.05 13.58,45.78 13.58,44.62 12.48,43.52 11.68,43.52 11.33,43.87 11.33,44.38 v1(11.65,44.7)
MDI_PHY0_2_P: length 24.5
  TOP w0.155: v1(14.23,38.56) 14.4,38.73 D34.2 14.4,40.97 13.96,41.41 13.96,43.67 14.4,44.12 D34.7 14.4,46.31 v1(14.23,46.48) ; R133.2 10.69,44.74 v1(10.73,44.7) ; T19.5 v1(10,35.54)
  ART04 w0.14: v1(14.23,46.48) 14.23,46.05 13.96,45.78 13.96,45.54 14.05,45.45 14.05,44.79 13.96,44.7 13.96,44.46 12.64,43.14 11.52,43.14 10.95,43.71 10.95,44.48 v1(10.73,44.7) ; v1(10,35.54) 9.69,35.85 9.69,36.05 10.19,36.55 13.21,36.55 13.96,37.3 13.96,38.28 v1(14.23,38.56)
MDI_PHY0_3_N: length 21.5
  TOP w0.155: v1(16.77,38.56) 16.94,38.73 D34.4 16.94,40.97 16.5,41.41 16.5,43.67 16.94,44.12 D34.5 16.94,45.54 16.48,46 16.48,47.27 15.9,47.85 14.95,47.85 R134.2 ; T19.3 v1(12,35.54)
  ART04 w0.14: v1(16.77,38.56) 16.5,38.28 16.5,35.77 15.19,34.47 12.72,34.47 12.31,34.88 12.31,35.23 v1(12,35.54)
MDI_PHY0_3_P: length 20.5
  TOP w0.155: v1(15.84,38.56) 15.67,38.73 D34.3 15.67,40.97 16.12,41.41 16.12,43.67 15.67,44.12 D34.6 15.67,45.54 16.1,45.97 16.1,47.11 15.74,47.47 14.96,47.47 R135.2 ; T19.2 v1(13,35.54)
  ART04 w0.14: v1(13,35.54) 12.69,35.23 12.69,35.03 12.87,34.85 15.04,34.85 15.21,35.02 15.21,35.22 15.13,35.3 15.13,35.5 15.32,35.7 15.52,35.7 15.6,35.61 15.8,35.61 16.12,35.93 16.12,36.67 15.98,36.81 15.91,36.81 15.77,36.95 15.77,37.23 15.91,37.37 15.98,37.37 16.12,37.51 16.12,38.28 v1(15.84,38.56)
MDI_PHY1_0_N: length 59.4
  TOP w0.155: v1(55.24,26.08) 55.01,26.31 55.01,26.53 R191.2 ; T20.12 18.93,38.78 18.75,38.96 D43.1 18.75,40.97 19.2,41.41 19.2,43.67 18.75,44.12 D43.8 18.75,45.85 19.2,46.3 19.2,47.47 19.57,47.85 19.92,47.85 v1(20.19,48.12)
  ART04 w0.14: v1(20.19,48.12) 20.47,47.85 20.91,47.85 21.34,47.42 21.34,42.47 27.17,36.64 33.54,34 34.24,33.3 34.81,31.92 35.54,31.2 38.28,30.06 44.93,30.06 52.01,27.13 54.6,27.13 54.96,26.76 54.96,26.36 v1(55.24,26.08)
MDI_PHY1_0_P: length 59.4
  TOP w0.155: v1(54.31,26.08) 54.54,26.31 54.54,26.53 R190.2 ; T20.11 19.93,38.73 20.02,38.82 D43.2 20.02,40.97 19.58,41.41 19.58,43.67 20.02,44.12 D43.7 20.02,45.82 19.58,46.26 19.58,47.31 19.73,47.47 19.92,47.47 v1(20.19,47.2)
  ART04 w0.14: v1(20.19,47.2) 20.47,47.47 20.75,47.47 20.95,47.27 20.95,45.23 20.82,45.09 20.61,45.09 20.47,44.95 20.47,44.67 20.61,44.53 20.82,44.53 20.95,44.39 20.95,44.11 20.82,43.97 20.61,43.97 20.47,43.83 20.47,43.55 20.61,43.41 20.82,43.41 20.95,43.27 20.95,42.31 26.95,36.32 33.32,33.68 33.92,33.08 34.49,31.7 35.32,30.87 38.21,29.68 44.86,29.68 51.94,26.75 54.44,26.75 54.58,26.61 54.58,26.36 v1(54.31,26.08)
MDI_PHY1_1_N: length 59.2
  TOP w0.155: v1(57.05,26.08) 56.82,26.31 56.82,26.53 R184.2 ; v1(22.73,48.12) 22.46,47.85 22.11,47.85 21.74,47.47 21.74,46.3 21.29,45.85 D43.6 21.29,44.12 21.74,43.67 21.74,41.41 21.29,40.97 D43.3 21.29,39.16 21.93,38.52 T20.9
  ART04 w0.14: v1(22.73,48.12) 23.01,47.85 23.45,47.85 23.88,47.42 23.88,43.13 29.56,37.45 33.77,35.7 34.56,34.92 36.16,32.53 37.01,31.67 38.17,31.19 46.07,31.19 47.48,30.61 49.29,30.61 50.62,30.05 52,28.68 54.77,28.68 55.61,27.83 55.81,27.83 56.77,26.87 56.77,26.36 v1(57.05,26.08)
MDI_PHY1_1_P: length 59.2
  TOP w0.155: v1(56.12,26.08) 56.35,26.31 56.35,26.53 R185.2 ; v1(22.73,47.2) 22.46,47.47 22.27,47.47 22.12,47.31 22.12,46.31 22.56,45.87 D43.5 22.56,44.12 22.12,43.67 22.12,41.41 22.56,40.97 D43.4 22.56,38.78 22.93,38.41 T20.8
  ART04 w0.14: v1(56.12,26.08) 56.39,26.36 56.39,26.71 55.65,27.45 55.45,27.45 54.61,28.3 51.84,28.3 50.41,29.73 49.21,30.23 47.41,30.23 45.99,30.81 38.1,30.81 36.79,31.35 35.86,32.28 34.26,34.68 33.56,35.38 29.34,37.13 23.5,42.97 23.5,43.53 23.36,43.67 23.13,43.67 22.99,43.81 22.99,44.09 23.13,44.23 23.36,44.23 23.5,44.37 23.5,44.64 23.36,44.78 23.13,44.78 22.99,44.92 22.99,45.2 23.13,45.34 23.36,45.34 23.5,45.48 23.5,47.27 23.29,47.47 23.01,47.47 v1(22.73,47.2)
MDI_PHY1_2_N: length 53.2
  TOP w0.155: v1(25.2,46.55) 25.02,46.38 D40.8 25.02,44.12 25.47,43.67 25.47,41.41 25.02,40.97 D40.1 25.02,38.54 24.93,38.44 T20.6 ; v1(59.25,26.08) 59.02,26.31 59.02,26.53 R186.2
  ART04 w0.14: v1(59.25,26.08) 58.98,26.36 58.98,27.31 57.33,28.96 47.04,33.22 46.54,33.22 43.94,34.3 40.09,38.14 38.43,38.83 38.4,38.86 34.34,38.86 28.4,44.81 28.16,44.81 26.55,46.42 26.55,46.72 26.3,46.97 25.62,46.97 v1(25.2,46.55)
MDI_PHY1_2_P: length 53.2
  TOP w0.155: v1(58.32,26.08) 58.55,26.31 58.55,26.53 R187.2 ; v1(26.12,46.55) 26.29,46.38 D40.7 26.29,44.12 25.85,43.67 25.85,41.41 26.29,40.97 D40.2 26.29,38.64 25.93,38.27 T20.5
  ART04 w0.14: v1(58.32,26.08) 58.59,26.36 58.59,27.16 57.11,28.64 46.96,32.84 46.46,32.84 43.72,33.98 39.88,37.82 38.29,38.48 37.77,38.48 37.63,38.34 37.07,38.34 36.93,38.48 36.65,38.48 36.51,38.34 36.51,38.29 36.37,38.15 36.09,38.15 35.95,38.29 35.95,38.34 35.81,38.48 35.53,38.48 35.39,38.34 35.39,38.29 35.25,38.15 34.97,38.15 34.84,38.29 34.84,38.34 34.7,38.48 34.18,38.48 28.24,44.42 28,44.42 27.67,44.75 27.48,44.75 27.39,44.67 27.19,44.67 26.99,44.86 26.99,45.06 27.08,45.15 27.08,45.35 26.88,45.55 26.69,45.54 26.6,45.46 26.4,45.46 26.2,45.65 26.2,45.85 26.29,45.94 26.29,46.14 26.12,46.31 v1(26.12,46.55)
MDI_PHY1_3_N: length 55.3
  TOP w0.155: v1(27.74,46.55) 27.56,46.38 D40.6 27.56,44.12 28.01,43.67 28.01,41.41 27.56,40.97 D40.3 27.56,38.68 27.93,38.31 T20.3 ; v1(61.45,26.08) 61.22,26.31 61.22,26.53 R188.2
  ART04 w0.14: v1(27.74,46.55) 28.04,46.85 28.04,47.26 28.48,47.7 31.75,47.7 34.87,44.58 34.87,41.91 35.13,41.66 41.16,39.16 43.71,36.61 46.68,35.38 47.61,34.45 49.32,33.74 49.7,33.36 51.94,32.44 53.81,32.44 57.47,30.92 58.4,29.99 59.93,29.36 61.18,28.11 61.18,26.36 v1(61.45,26.08)
MDI_PHY1_3_P: length 55.3
  TOP w0.155: v1(60.53,26.08) 60.75,26.31 60.75,26.53 R189.2 ; v1(28.66,46.55) 28.83,46.38 D40.5 28.83,44.12 28.39,43.67 28.39,41.41 28.83,40.97 D40.4 28.83,38.48 28.93,38.39 T20.2
  ART04 w0.14: v1(60.53,26.08) 60.8,26.36 60.8,27.95 59.71,29.04 58.18,29.67 57.26,30.6 53.73,32.05 51.86,32.05 49.49,33.04 49.11,33.42 47.39,34.13 46.46,35.06 43.49,36.29 40.95,38.83 34.91,41.33 34.49,41.75 34.49,44.42 34.01,44.91 33.83,44.91 33.7,44.78 33.53,44.78 33.41,44.9 33.41,45.08 33.54,45.2 33.54,45.38 33.41,45.5 33.24,45.5 33.11,45.37 32.94,45.37 32.81,45.49 32.81,45.67 32.94,45.8 32.94,45.97 31.59,47.32 30.36,47.32 30.23,47.2 30.23,47.19 30.11,47.07 29.94,47.07 29.81,47.19 29.81,47.2 29.69,47.32 28.64,47.32 28.42,47.1 28.42,46.79 v1(28.66,46.55)
MIPI_DSI_CK_N: length 46.5
  TOP w0.155: v1(2.76,65.71) 2.52,65.96 1.6,65.96 1.49,65.85 J10.25 ; J16.262 32.25,49.73 32.31,49.78 32.31,50.58 v1(32.04,50.85)
  ART04 w0.14: v1(2.76,65.71) 2.52,65.96 2.04,65.96 1.64,65.56 1.64,64.96 4.75,61.85 5.51,61.85 5.65,61.99 5.65,62.12 5.79,62.26 6.07,62.26 6.2,62.12 6.2,61.99 6.34,61.85 6.62,61.85 6.76,61.99 6.76,62.12 6.9,62.26 7.18,62.26 7.32,62.12 7.32,61.99 7.46,61.85 7.74,61.85 7.88,61.99 7.88,62.12 8.02,62.26 8.3,62.26 8.44,62.12 8.44,61.99 8.58,61.85 8.86,61.85 9,61.99 9,62.12 9.14,62.26 9.42,62.26 9.56,62.12 9.56,61.99 9.7,61.85 11.96,61.85 14.36,60.86 15.92,59.3 17.09,56.47 21.31,52.25 28.42,49.3 31.87,49.3 32.34,49.77 32.34,50.55 v1(32.04,50.85)
MIPI_DSI_CK_P: length 46.5
  TOP w0.155: J10.27 1.44,66.45 1.55,66.34 2.47,66.34 v1(2.76,66.64) ; v1(32.96,50.85) 32.69,50.58 32.69,49.76 32.75,49.7 J16.260
  ART04 w0.14: v1(32.96,50.85) 32.96,50.72 32.72,50.48 32.72,49.61 32.03,48.92 28.35,48.92 21.1,51.92 16.76,56.26 15.59,59.08 14.14,60.53 11.88,61.47 4.59,61.47 1.26,64.8 1.26,65.72 1.88,66.34 2.47,66.34 v1(2.76,66.64)
MIPI_DSI_D0_N: length 47.2
  TOP w0.155: J10.34 4.38,68.55 4.49,68.66 5.16,68.66 v1(5.44,68.39) ; v1(38.04,50.85) 38.31,50.58 38.31,49.71 38.25,49.66 J16.238
  ART04 w0.14: v1(38.04,50.85) 38.31,51.12 38.31,51.93 38.61,52.65 38.61,54.69 37.88,56.46 36.31,58.03 32.23,59.72 30.77,59.72 27.84,60.93 25.01,63.76 21.87,65.86 14.25,69.01 13.75,69.01 13.61,68.87 13.61,68.83 13.48,68.69 13.2,68.69 13.06,68.83 13.06,68.87 12.92,69.01 12.64,69.01 12.5,68.87 12.5,68.83 12.36,68.69 12.08,68.69 11.94,68.83 11.94,68.87 11.8,69.01 9.97,69.01 8.32,69.7 7.1,69.7 6.06,68.66 5.71,68.66 v1(5.44,68.39)
MIPI_DSI_D0_P: length 47.2
  TOP w0.155: v1(5.44,69.31) 5.16,69.04 4.49,69.04 4.38,69.15 J10.36 ; J16.236 38.75,49.64 38.69,49.7 38.69,50.58 v1(38.96,50.85)
  ART04 w0.14: v1(5.44,69.31) 5.71,69.04 5.91,69.04 6.94,70.08 8.39,70.08 10.05,69.39 14.33,69.39 22.05,66.19 25.25,64.05 28.06,61.25 30.84,60.1 32.31,60.1 36.53,58.35 38.2,56.68 38.99,54.77 38.99,52.57 38.69,51.85 38.69,51.12 v1(38.96,50.85)
MIPI_DSI_D1_N: length 46.7
  TOP w0.155: J16.244 36.75,49.73 36.8,49.78 36.8,50.96 37.29,51.44 37.29,52.2 37.14,52.35 37,52.35 v1(36.78,52.13) ; v1(5.44,64.79) 5.16,65.06 4.38,65.06 4.27,64.95 J10.22
  ART04 w0.14: v1(36.78,52.13) 36.51,52.41 36.13,52.41 34.95,53.59 34.95,53.92 33.09,55.78 31.75,55.78 31.27,56.26 28.98,56.26 27.7,57.53 27.51,57.53 27.27,57.3 26.75,57.3 26.33,57.72 26.33,58.23 26.57,58.47 26.57,58.67 25.68,59.55 25.49,59.55 24.73,58.79 24.21,58.79 23.79,59.21 23.79,59.73 24.55,60.49 24.55,60.68 24,61.24 21.53,61.24 20.62,62.15 13.7,65.02 12.19,65.02 11.91,64.74 11.63,64.74 11.35,65.02 11.08,65.02 10.8,64.74 10.52,64.74 10.24,65.02 9.96,65.02 9.68,64.74 9.4,64.74 9.12,65.02 5.67,65.02 v1(5.44,64.79)
MIPI_DSI_D1_P: length 46.7
  TOP w0.155: v1(5.44,65.71) 5.17,65.44 4.33,65.44 4.23,65.55 J10.24 ; v1(36.78,53.06) 37.11,52.73 37.3,52.73 37.67,52.36 37.67,51.28 37.19,50.8 37.19,49.73 37.25,49.7 J16.242
  ART04 w0.14: v1(5.44,65.71) 5.74,65.41 13.77,65.41 20.83,62.48 21.69,61.62 24.16,61.62 24.93,60.84 24.93,60.33 24.17,59.57 24.17,59.37 24.37,59.17 24.57,59.17 25.33,59.93 25.84,59.93 26.95,58.82 26.95,58.31 26.71,58.07 26.71,57.87 26.91,57.68 27.11,57.68 27.35,57.92 27.86,57.92 29.13,56.64 31.42,56.64 31.91,56.16 33.25,56.16 35.33,54.08 35.33,53.75 36.29,52.79 36.51,52.79 v1(36.78,53.06)
MIPI_DSI_D2_N: length 47.1
  TOP w0.155: J16.250 35.25,49.99 35.04,50.2 35.04,50.61 35.51,51.08 v1(35.51,51.3) ; J10.28 4.38,66.75 4.49,66.86 5.16,66.86 v1(5.44,66.59)
  ART04 w0.14: v1(35.51,51.3) 35.78,51.04 36.71,51.04 37.31,51.64 37.31,53.49 33.94,56.86 32.12,56.86 29.03,58.13 24.51,62.66 21.83,64.45 18.81,65.7 18.63,65.62 18.57,65.48 18.09,65.28 17.54,65.51 17.35,65.98 17.41,66.13 17.33,66.31 17.07,66.42 16.89,66.34 16.83,66.2 16.36,66 15.81,66.23 15.61,66.7 15.67,66.85 15.59,67.03 14.25,67.59 12.22,67.59 12.03,67.39 11.67,67.39 11.47,67.59 7.77,67.59 7.04,66.86 5.71,66.86 v1(5.44,66.59)
MIPI_DSI_D2_P: length 47.1
  TOP w0.155: v1(5.44,67.51) 5.16,67.24 4.49,67.24 4.38,67.35 J10.30 ; v1(35.51,50.38) 35.75,50.14 J16.248
  ART04 w0.14: v1(5.44,67.51) 5.71,67.24 6.88,67.24 7.61,67.97 14.33,67.97 15.89,67.32 16.08,66.85 16.02,66.7 16.1,66.52 16.36,66.41 16.54,66.49 16.6,66.64 17.07,66.83 17.62,66.6 17.82,66.13 17.76,65.98 17.83,65.8 18.09,65.69 18.28,65.77 18.34,65.92 18.81,66.11 22.01,64.78 24.75,62.95 29.25,58.46 32.2,57.24 34.1,57.24 37.69,53.65 37.69,51.48 36.87,50.66 35.78,50.66 v1(35.51,50.38)
MIPI_DSI_D3_N: length 46
  TOP w0.155: v1(33.54,52.3) 33.81,52.03 33.81,49.73 33.75,49.68 J16.256 ; J10.31 1.49,67.65 1.6,67.76 2.52,67.76 v1(2.76,67.51)
  ART04 w0.14: v1(2.76,67.51) 3.04,67.78 3.23,67.78 3.71,67.31 3.71,64.13 4.36,63.47 6.88,63.47 7.41,62.94 15.87,62.94 16.25,62.79 16.32,62.6 16.31,62.57 16.38,62.39 16.64,62.28 16.82,62.35 16.84,62.39 17.02,62.47 17.28,62.36 17.35,62.18 17.34,62.14 17.42,61.96 17.67,61.85 17.86,61.93 17.87,61.96 18.05,62.04 19.38,61.49 25.62,55.24 30.75,55.24 32.43,53.57 33.5,53.57 33.83,53.24 33.83,52.59 v1(33.54,52.3)
MIPI_DSI_D3_P: length 46
  TOP w0.155: J10.33 1.44,68.25 1.55,68.14 2.47,68.14 v1(2.76,68.44) ; v1(34.46,52.3) 34.19,52.02 34.19,49.78 34.19,49.78 34.19,49.68 34.25,49.62 J16.254
  ART04 w0.14: v1(2.76,68.44) 3.04,68.17 3.39,68.17 4.09,67.47 4.09,64.29 4.52,63.86 7.04,63.86 7.57,63.32 15.95,63.32 19.59,61.81 25.78,55.63 30.91,55.63 32.59,53.95 33.66,53.95 34.21,53.4 34.21,52.55 v1(34.46,52.3)
MIPI_DSI_SCL: length 123.9
  TOP w0.203: J16.231 40,53.9 v1(40.72,53.19) ; R610.2 v1(101.73,116.97) R604.1
  ART04 w0.203: v1(101.73,116.97) 102.22,116.48 102.22,115.47 102.01,115.27 100.47,115.27 96.79,111.58 91.86,111.58 89.97,109.69 89.97,109.1 89.35,108.48 88.95,108.48 88.4,109.04 87.29,109.04 86.27,110.06 81.04,110.06 80.76,109.78 79.58,109.78 73.81,104.01 72.64,104.01 63.85,95.22 63.85,86.16 62.31,84.62 62.31,80.1 61.93,79.72 61.93,75.82 63.34,74.41 v1(66.9,74.41)
  BOTTOM w0.203: v1(66.9,74.41) 66.19,75.12 66.19,76.73 65.61,77.32 60.57,77.32 51.51,68.26 51.51,66.04 50.06,64.59 50.06,58.9 47.83,56.67 43.41,56.67 40.72,53.97 v1(40.72,53.19)
MIPI_DSI_SCL_R: length 159.1
  TOP w0.203: R428.1 v1(9.27,72.01) ; R608.1 110.78,117.25 110.32,116.78 U23.7 107.71,116.78 v1(107.65,116.84)
  ART03 w0.203: v1(46.23,107.44) 47.24,108.46 74.19,108.46 77.49,111.76 77.49,111.96 83.9,118.38 88.2,118.38 88.7,117.88 95.96,117.88 96.38,118.3 99.47,118.3 100.27,117.5 105.68,117.5 105.81,117.63 106.87,117.63 v1(107.65,116.84)
  ART04 w0.203: v1(9.27,72.01) 7.92,72.01 4.65,75.29 1.35,75.29 0.71,75.92 0.71,77.22 1.79,78.3 1.79,79.3 5.65,83.17 11.32,83.17 12.29,82.19 14.6,82.19 14.93,82.52 21.44,82.52 22.66,81.31 36.53,81.31 36.75,81.53 43.68,81.53 46.6,84.45 46.7,84.45 48.56,86.32 48.56,104.57 46.23,106.91 v1(46.23,107.44)
MIPI_DSI_SDA: length 98.5
  TOP w0.203: J16.229 40.59,56.41 40.59,56.74 40.54,56.78 40.54,57.76 40.28,58.01 40.28,60.13 41.09,60.93 41.38,60.93 50.75,70.31 50.75,70.47 51.84,71.56 52.58,71.56 v1(61.32,80.3) ; R605.1 v1(101.73,115.95) R611.2
  ART04 w0.203: v1(101.73,115.95) 100.51,115.95 96.6,112.04 91.67,112.04 89.13,109.5 87.48,109.5 86.46,110.52 80.85,110.52 80.57,110.24 78.92,110.24 73.63,104.95 72.7,104.95 63.28,95.53 63.28,90.23 61.82,88.77 61.82,80.81 v1(61.32,80.3)
MIPI_DSI_SDA_R: length 146.2
  TOP w0.203: v1(3.68,77.07) 3.43,76.82 R427.2 ; R609.1 110.49,116.33 110.29,116.13 U23.6 108.22,116.13 v1(107.65,115.57)
  ART03 w0.203: v1(107.65,115.57) 106.74,116.48 100.64,116.48 99.28,117.84 97.7,117.84 95.96,116.1 95.56,116.1 94.84,116.82 88.64,116.82 87.54,117.92 84.09,117.92 77.94,111.77 77.94,111.57 73.82,107.44 v1(47.24,107.44)
  ART04 w0.203: v1(3.68,77.07) 5.81,79.19 5.81,80.28 6.91,81.38 7.31,81.38 7.57,81.13 10.92,81.13 11.66,80.39 20.79,80.39 21.24,79.93 37.8,79.93 38,80.14 45.42,80.14 49.3,84.02 49.3,104.9 47.24,106.96 v1(47.24,107.44)
MIPI_GPIO: length 106.6
  TOP w0.203: R638.1 116.95,57.25 117.15,57.45 117.15,60.19 v1(117.09,60.25) ; v1(66.01,78.27) 62.83,78.27 54.37,69.81 51.56,69.81 41.77,60.02 41.47,60.02 41.2,59.75 41.2,58.61 41.46,58.35 41.46,56.78 41.41,56.73 41.41,56.41 J16.225
  ART04 w0.203: v1(117.09,60.25) 117.09,62.1 116.88,62.32 116.88,68.42 114.56,70.74 109.15,70.74 108.66,71.22 102.45,71.22 101.87,71.81 97.3,71.81 96.16,72.95 90.33,72.95 89.89,72.51 89.89,71.92 89.49,71.53 86.07,71.53 85.31,72.28 85.21,72.28 85.04,72.45 85.04,72.83 84.77,73.1 82.55,73.1 82.15,73.51 81.58,73.51 81.17,73.91 80.36,73.91 77.21,77.06 75.29,77.06 74.53,77.81 68.79,77.81 67.36,76.38 66.49,76.38 66.01,76.85 v1(66.01,78.27)
MIPI_GPIO_R: length 166.7
  TOP w0.203: U32.10 115.12,64.84 v1(115.45,64.52) ; R426.2 v1(1.65,76.31)
  ART04 w0.203: v1(47.96,83.85) 47.34,83.24 46.71,83.24 44.07,80.59 37.81,80.59 37.73,80.52 37.41,80.52 37.29,80.39 22.28,80.39 21.06,81.61 15.6,81.61 15.27,81.28 11.41,81.28 11.11,81.58 7.76,81.58 7.5,81.84 6.52,81.84 4.31,79.63 4.31,78.97 v1(1.65,76.31)
  BOTTOM w0.203: v1(47.96,83.85) 50.16,86.06 73.26,86.06 73.49,86.28 75.03,86.28 78.26,89.51 78.26,99.35 81.67,102.77 86.6,102.77 87.43,103.59 87.43,103.66 87.8,104.03 89.14,104.03 92.18,100.98 92.18,99.47 92.58,99.07 92.58,94.94 93.69,93.83 97.05,93.83 100.38,90.5 101.02,90.5 103.12,88.4 103.12,85.59 104.03,84.68 104.12,84.68 104.75,84.05 104.75,83.24 105.13,82.85 105.13,81.7 104.67,81.24 104.67,76.39 104.75,76.31 104.75,75.93 103.61,74.79 103.61,73.97 102.97,73.33 102.97,71.58 104.19,70.36 107.75,70.36 112.83,65.28 114.69,65.28 v1(115.45,64.52)
PCA9555A_A0: length 5.4
  TOP w0.203: U19.21 113.53,93.99 112.76,93.99 111.86,93.09 R537.2 111.35,92.81 111.12,92.58 109.55,92.58 109.27,92.86 R532.1
PCA9555A_A1: length 5.8
  TOP w0.203: U19.2 120.42,92.74 120.85,92.3 120.85,91.68 121.38,91.16 R536.2 121.54,90.86 121.74,90.65 123.37,90.65 123.62,90.91 R533.1
PCA9555A_A2: length 5.3
  TOP w0.203: U19.3 120.35,93.39 121.54,92.2 R535.2 121.54,91.87 121.74,91.67 123.37,91.67 123.62,91.92 R534.1
PCB_ID0: length 5.4
  TOP w0.203: U19.16 112.24,97.29 R527.2 111.35,97.89 111.12,97.66 109.55,97.66 109.27,97.94 R511.1
PCB_ID1: length 5.2
  TOP w0.203: U19.17 111.87,96.64 R528.2 111.35,96.88 111.12,96.65 109.55,96.65 109.27,96.93 R512.1
PCB_ID2: length 5.1
  TOP w0.203: U19.18 112.01,95.99 111.86,96.14 R529.2 111.35,95.86 111.12,95.63 109.55,95.63 109.27,95.91 R513.1
PCIE_EP_RC_FLAG: length 2.6
  TOP w0.203: R35.2 99.92,57.61 100,57.53 J16.313
PCIE_RX_N/SATA_B_P: length 16.3
  TOP w0.188: v1(119.55,33.61) 119.81,33.35 120.28,33.35 120.33,33.39 J1.41 ; R30.2 v1(112.65,35.15)
  ART04 w0.173: v1(119.55,33.61) 119.28,33.34 117.19,33.34 116.56,33.97 116.56,34.67 113.28,37.95 112.04,37.95 111.46,37.36 111.46,35.99 111.95,35.49 112.35,35.49 112.65,35.2 v1(112.65,35.15)
PCIE_RX_P/SATA_B_N: length 15
  TOP w0.188: R31.2 v1(112.65,36.17) ; v1(119.55,32.68) 119.81,32.94 120.28,32.94 120.33,32.9 J1.43
  ART04 w0.173: v1(112.65,36.17) 112.35,35.87 112.11,35.87 111.84,36.15 111.84,37.21 112.2,37.57 113.13,37.57 116.18,34.51 116.18,33.81 117.03,32.95 119.28,32.95 v1(119.55,32.68)
PCIE_TX_N/SATA_A_N: length 98
  TOP w0.188: v1(118.11,32.11) 118.37,31.85 120.28,31.85 120.33,31.9 J1.47 ; C6.2 92.74,63.92 92.74,65.26 v1(93,65.53)
  ART03 w0.173: v1(93,65.53) 92.73,65.81 92.73,66.38 91.32,67.79 89.71,67.79 88.95,68.55 81,68.55 77.11,64.67 77.11,51.66 77.34,51.44 77.34,42.63 79.36,40.61 93.39,40.61 94.89,39.12 96.13,39.12 98.6,36.65 104.77,36.65 106.31,35.11 107.08,35.11 107.88,34.3 107.88,33.2 109.13,31.95 112.19,31.95 114.17,29.97 119.19,29.97 119.69,30.47 119.69,31.37 119.23,31.84 118.38,31.84 v1(118.11,32.11)
PCIE_TX_P/SATA_A_P: length 97.9
  TOP w0.188: C1.2 92.35,63.93 92.35,65.25 v1(92.08,65.53) ; J1.49 120.34,31.39 120.27,31.47 118.4,31.47 v1(118.11,31.18)
  ART03 w0.173: v1(92.08,65.53) 92.34,65.8 92.34,66.23 91.16,67.41 89.55,67.41 88.79,68.17 81.16,68.17 77.5,64.51 77.5,51.82 77.72,51.59 77.72,42.78 79.51,40.99 93.55,40.99 93.85,40.7 94.09,40.7 94.11,40.72 94.36,40.72 94.6,40.48 94.6,40.23 94.58,40.21 94.58,39.96 95.05,39.5 96.29,39.5 96.5,39.29 96.98,39.29 97.23,39.04 97.23,38.56 97.47,38.31 97.95,38.31 98.2,38.07 98.2,37.59 98.76,37.03 104.92,37.03 106.47,35.49 107.24,35.49 108.26,34.46 108.26,33.36 109.29,32.33 112.34,32.33 112.44,32.24 112.87,32.24 113.14,31.96 113.14,31.54 114.33,30.35 114.77,30.35 114.94,30.52 114.94,30.87 115.11,31.04 115.46,31.04 115.63,30.87 115.63,30.52 115.8,30.35 116.15,30.35 116.32,30.52 116.32,30.87 116.49,31.04 116.84,31.04 117.01,30.87 117.01,30.52 117.18,30.35 119.03,30.35 119.31,30.63 119.31,31.22 119.07,31.45 118.38,31.45 v1(118.11,31.18)
PHY0_MDI0_N: length 31.5
  TOP w0.508: T19.13 v1(3,26.42)
  ART04 w0.356: J17.2 15.46,12.55 4.51,12.55 2.87,14.19 2.87,16.32 4.79,18.24 4.79,26.72 4.26,27.24 3.57,27.24 3,26.67 v1(3,26.42)
PHY0_MDI0_P: length 31.5
  TOP w0.508: T19.14 v1(4,26.42)
  ART04 w0.356: J17.1 14.88,11.35 14.44,11.79 4.19,11.79 2.1,13.88 2.1,16.63 4.02,18.55 4.02,20.3 3.67,20.66 3.41,20.66 3.06,21.01 3.06,21.72 3.41,22.08 3.67,22.08 4.02,22.43 4.02,23.15 3.67,23.5 3.41,23.5 3.06,23.86 3.06,24.57 3.41,24.92 3.67,24.92 4.02,25.28 4.02,26.4 v1(4,26.42)
PHY0_MDI1_N: length 35.1
  TOP w0.508: T19.16 v1(6,26.42)
  ART03 w0.356: J17.6 20.19,12.2 19.46,12.2 18.47,11.2 18.47,9.85 18.18,9.56 18.18,9.54 17.2,8.56 13.68,8.56 12.75,9.49 12.75,10.75 11.66,11.84 7.98,11.84 5.79,14.03 5.79,26.22 v1(6,26.42)
PHY0_MDI1_P: length 35.2
  TOP w0.508: T19.17 v1(7,26.42)
  ART03 w0.356: v1(7,26.42) 7,26.66 6.53,27.12 6.53,28.1 7.04,28.6 7.57,28.6 7.9,28.27 7.9,24.87 6.56,23.52 6.56,23.07 6.91,22.72 6.91,21.65 6.56,21.29 6.56,20.23 6.91,19.87 6.91,18.81 6.56,18.45 6.56,17.38 6.91,17.03 6.91,15.96 6.56,15.61 6.56,14.34 8.29,12.6 11.98,12.6 13.52,11.06 13.52,9.8 13.99,9.33 16.89,9.33 17.42,9.86 J17.3
PHY0_MDI2_N: length 29.3
  TOP w0.508: T19.19 v1(9,29.37)
  ART04 w0.356: J17.5 19.69,10.69 17.46,12.92 17.46,13.84 16.61,14.69 10.68,14.69 8.85,16.52 8.85,18.95 10.02,20.12 10.02,27.37 9.11,28.28 9.11,29.25 v1(9,29.37)
